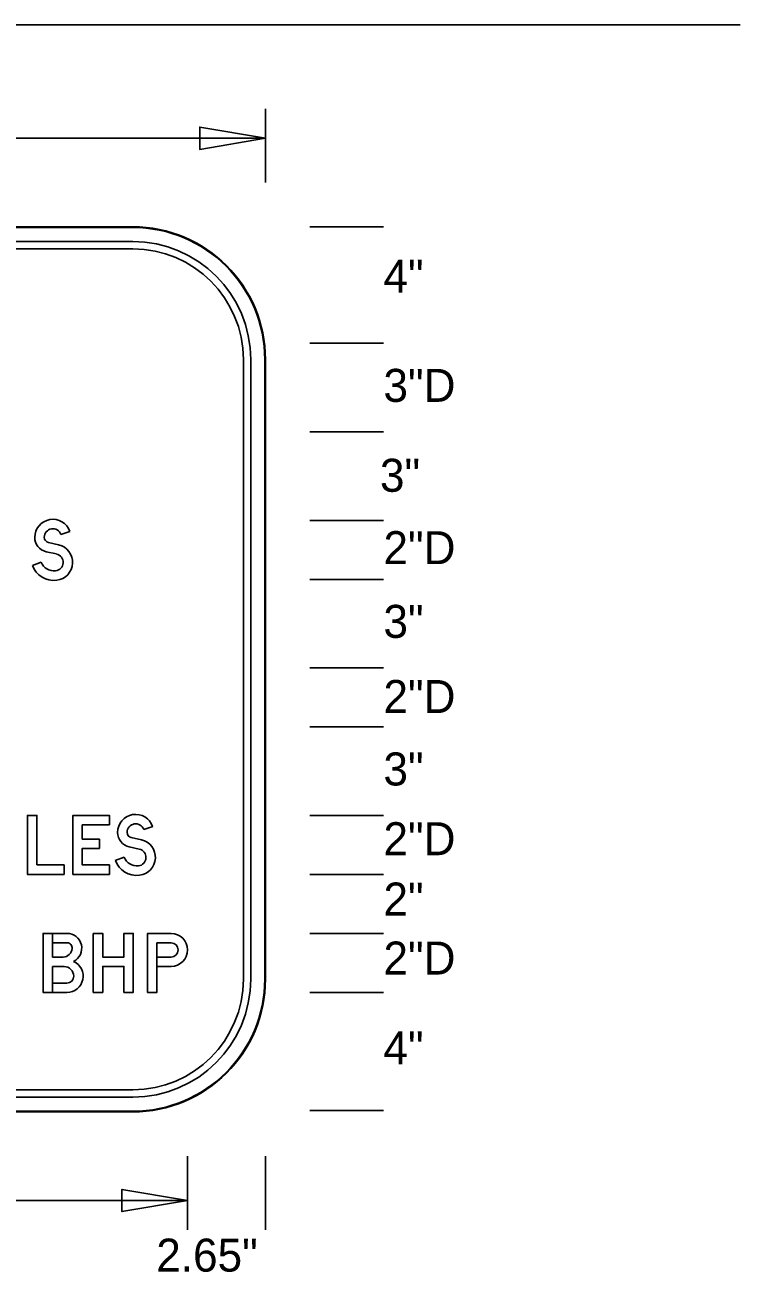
# Model space of a CAD drawing. Extents: x 0 to 770, y 0 to 495.
# Drawn here: x 694.1 to 770, y 197.7 to 330 of the extents above; entities that cross this region are included whole.
import ezdxf

# ---------------------------------------------------------------- set-up
doc = ezdxf.new("R2010")
doc.units = 0
for name, color, linetype in [('Default', 7, 'Continuous'), ('Dimension', 7, 'Continuous'), ('GSBWFill', 7, 'Continuous'), ('GSColorFill', 7, 'Continuous'), ('GSDims', 7, 'Continuous'), ('GSOutline', 7, 'Continuous'), ('SheetLines_dp', 7, 'Continuous')]:
    doc.layers.add(name, color=color, linetype=linetype)

msp = doc.modelspace()

# ---------------------------------------------------------------- linework, layer by layer
at = {"layer": 'Default'}
for p, q in [((697.92, 275.94), (698.86, 276.27)), ((697.92, 275.94), (698.86, 276.27)), ((697.92, 275.94), (698.86, 276.27)), ((696.37, 274.11), (697.45, 273.87)), ((696.37, 274.11), (697.45, 273.87)), ((696.37, 274.11), (697.45, 273.87)), ((697.67, 274.84), (696.59, 275.09)), ((697.67, 274.84), (696.59, 275.09)), ((697.67, 274.84), (696.59, 275.09)), ((695.84, 273), (694.9, 272.65)), ((695.84, 273), (694.9, 272.65)), ((695.84, 273), (694.9, 272.65)), ((706.71, 244.63), (707.66, 244.96)), ((706.71, 244.63), (707.66, 244.96)), ((706.71, 244.63), (707.66, 244.96)), ((706.47, 243.54), (705.39, 243.79)), ((706.47, 243.54), (705.39, 243.79)), ((706.47, 243.54), (705.39, 243.79)), ((705.16, 242.81), (706.24, 242.56)), ((705.16, 242.81), (706.24, 242.56)), ((705.16, 242.81), (706.24, 242.56)), ((704.63, 241.7), (703.69, 241.35)), ((704.63, 241.7), (703.69, 241.35)), ((704.63, 241.7), (703.69, 241.35)), ((698.56, 232.61), (697.03, 232.61)), ((708.11, 232.61), (709.61, 232.61)), ((708.11, 232.61), (709.61, 232.61)), ((697.03, 230.11), (698.25, 230.11)), ((697.03, 230.11), (698.25, 230.11)), ((697.03, 230.11), (698.25, 230.11)), ((708.11, 230.11), (709.61, 230.11)), ((696.02, 227.35), (698.56, 227.35))]:
    msp.add_line(p, q, dxfattribs=at)
for points in [[(695.37, 240.88), (698.25, 240.88), (698.25, 239.87), (694.37, 239.87), (694.37, 246.13), (695.37, 246.13)], [(695.37, 240.88), (698.25, 240.88), (698.25, 239.87), (694.37, 239.87), (694.37, 246.13), (695.37, 246.13)], [(695.37, 240.88), (698.25, 240.88), (698.25, 239.87), (694.37, 239.87), (694.37, 246.13), (695.37, 246.13)], [(703.07, 245.13), (700.19, 245.13), (700.19, 243.63), (702.01, 243.63), (702.01, 242.63), (700.19, 242.63), (700.19, 240.88), (703.07, 240.88), (703.07, 239.87), (699.19, 239.87), (699.19, 246.13), (703.07, 246.13)], [(703.07, 245.13), (700.19, 245.13), (700.19, 243.63), (702.01, 243.63), (702.01, 242.63), (700.19, 242.63), (700.19, 240.88), (703.07, 240.88), (703.07, 239.87), (699.19, 239.87), (699.19, 246.13), (703.07, 246.13)], [(703.07, 245.13), (700.19, 245.13), (700.19, 243.63), (702.01, 243.63), (702.01, 242.63), (700.19, 242.63), (700.19, 240.88), (703.07, 240.88), (703.07, 239.87), (699.19, 239.87), (699.19, 246.13), (703.07, 246.13)], [(701.35, 233.61), (702.35, 233.61), (702.35, 231.11), (704.6, 231.11), (704.6, 233.61), (705.6, 233.61), (705.6, 227.35), (704.6, 227.35), (704.6, 230.11), (702.35, 230.11), (702.35, 227.35), (701.35, 227.35)], [(701.35, 233.61), (702.35, 233.61), (702.35, 231.11), (704.6, 231.11), (704.6, 233.61), (705.6, 233.61), (705.6, 227.35), (704.6, 227.35), (704.6, 230.11), (702.35, 230.11), (702.35, 227.35), (701.35, 227.35)], [(701.35, 233.61), (702.35, 233.61), (702.35, 231.11), (704.6, 231.11), (704.6, 233.61), (705.6, 233.61), (705.6, 227.35), (704.6, 227.35), (704.6, 230.11), (702.35, 230.11), (702.35, 227.35), (701.35, 227.35)]]:
    msp.add_lwpolyline(points, close=True, dxfattribs=at)
for points in [[(698.56, 233.61), (696.02, 233.61), (696.02, 227.35)], [(698.15, 231.11), (697.03, 231.11), (697.03, 233.61), (696.02, 233.61), (696.02, 227.35), (697.03, 227.35), (697.03, 230.11)], [(698.15, 231.11), (697.03, 231.11), (697.03, 233.61), (696.02, 233.61), (696.02, 227.35), (697.03, 227.35), (697.03, 230.11)], [(698.56, 233.61), (697.03, 233.61), (697.03, 232.61), (698.56, 232.61)], [(698.56, 233.61), (697.03, 233.61), (697.03, 232.61), (698.56, 232.61)], [(709.61, 233.61), (707.11, 233.61), (707.11, 227.35), (708.11, 227.35), (708.11, 230.11)], [(709.61, 233.61), (707.11, 233.61), (707.11, 227.35), (708.11, 227.35), (708.11, 232.61)], [(709.61, 233.61), (707.11, 233.61), (707.11, 227.35), (708.11, 227.35), (708.11, 232.61)], [(697.03, 232.61), (697.03, 231.11), (698.15, 231.11)], [(709.61, 231.11), (708.11, 231.11), (708.11, 232.61), (709.61, 232.61)], [(709.61, 231.11), (708.11, 231.11), (708.11, 230.11), (709.61, 230.11)], [(709.61, 231.11), (708.11, 231.11), (708.11, 230.11), (709.61, 230.11)], [(698.56, 228.35), (697.03, 228.35), (697.03, 230.11)], [(698.56, 228.35), (697.03, 228.35), (697.03, 227.35), (698.56, 227.35)], [(698.56, 228.35), (697.03, 228.35), (697.03, 227.35), (698.56, 227.35)]]:
    msp.add_lwpolyline(points, dxfattribs=at)
for centre, radius, start, end in [((697.06, 275.64), 1.91, 19.1395, 180), ((697.06, 275.64), 1.91, 19.1395, 180), ((697.06, 275.64), 1.91, 19.1395, 180), ((697.06, 275.64), 0.908, 19.1395, 180), ((697.06, 275.64), 0.908, 19.1395, 180), ((697.06, 275.64), 0.908, 19.1395, 180), ((696.71, 275.64), 1.57, 180, 257.1915), ((696.71, 275.64), 1.57, 180, 257.1915), ((696.71, 275.64), 1.57, 180, 257.1915), ((696.71, 275.64), 0.563, 180, 257.1915), ((696.71, 275.64), 0.563, 180, 257.1915), ((696.71, 275.64), 0.563, 180, 257.1915), ((697.25, 272.98), 1.91, 276.7854, 77.1915), ((697.25, 272.98), 1.91, 276.7854, 77.1915), ((697.25, 272.98), 1.91, 276.7854, 77.1915), ((697.18, 273.51), 2.44, 200.6442, 276.7854), ((697.18, 273.51), 2.44, 200.6442, 276.7854), ((697.18, 273.51), 2.44, 200.6442, 276.7854), ((697.18, 273.51), 1.44, 200.6442, 276.7854), ((697.18, 273.51), 1.44, 200.6442, 276.7854), ((697.18, 273.51), 1.44, 200.6442, 276.7854), ((697.25, 272.98), 0.908, 276.7854, 77.1915), ((697.25, 272.98), 0.908, 276.7854, 77.1915), ((697.25, 272.98), 0.908, 276.7854, 77.1915), ((705.85, 244.33), 1.91, 19.1395, 180), ((705.85, 244.33), 1.91, 19.1395, 180), ((705.85, 244.33), 1.91, 19.1395, 180), ((705.85, 244.33), 0.908, 19.1395, 180), ((705.85, 244.33), 0.908, 19.1395, 180), ((705.85, 244.33), 0.908, 19.1395, 180), ((705.51, 244.33), 1.57, 180, 257.1915), ((705.51, 244.33), 1.57, 180, 257.1915), ((705.51, 244.33), 1.57, 180, 257.1915), ((705.51, 244.33), 0.563, 180, 257.1915), ((705.51, 244.33), 0.563, 180, 257.1915), ((705.51, 244.33), 0.563, 180, 257.1915), ((706.04, 241.68), 1.91, 276.7854, 77.1915), ((706.04, 241.68), 1.91, 276.7854, 77.1915), ((706.04, 241.68), 1.91, 276.7854, 77.1915), ((706.04, 241.68), 0.908, 276.7854, 77.1915), ((706.04, 241.68), 0.908, 276.7854, 77.1915), ((706.04, 241.68), 0.908, 276.7854, 77.1915), ((705.98, 242.21), 2.44, 200.6442, 276.7854), ((705.98, 242.21), 2.44, 200.6442, 276.7854), ((705.98, 242.21), 2.44, 200.6442, 276.7854), ((705.98, 242.21), 1.44, 200.6442, 276.7854), ((705.98, 242.21), 1.44, 200.6442, 276.7854), ((705.98, 242.21), 1.44, 200.6442, 276.7854), ((709.61, 231.86), 1.75, 270, 90), ((709.61, 231.86), 1.75, 270, 90), ((709.61, 231.86), 1.75, 270, 90), ((709.61, 231.86), 0.751, 270, 90), ((709.61, 231.86), 0.751, 270, 90), ((709.61, 231.86), 0.751, 270, 90)]:
    msp.add_arc(centre, radius, start, end, dxfattribs=at)
for centre, major_axis, start_param, end_param in [((698.56, 232.05), (0, 1.57), 3.604547, 6.283185), ((698.56, 232.05), (0, 1.57), 3.604547, 6.283185), ((698.56, 232.05), (0, 1.57), 3.604547, 6.283185), ((698.15, 232.08), (0, 0.97), 3.141593, 4.63539), ((698.15, 232.08), (0, 0.97), 3.141593, 4.63539), ((698.15, 232.08), (0, 0.97), 3.141593, 4.63539), ((698.56, 232.05), (0, 0.563), 4.63539, 6.283185), ((698.56, 232.05), (0, 0.563), 4.63539, 6.283185), ((698.56, 232.05), (0, 0.563), 4.63539, 6.283185), ((698.56, 229.07), (0, 1.72), 3.141593, 5.865119), ((698.56, 229.07), (0, 1.72), 3.141593, 5.865119), ((698.56, 229.07), (0, 1.72), 3.141593, 5.865119), ((698.25, 229.07), (0, 1.03), 4.712389, 6.283185), ((698.25, 229.07), (0, 1.03), 4.712389, 6.283185), ((698.25, 229.07), (0, 1.03), 4.712389, 6.283185), ((698.56, 229.07), (0, 0.72), 3.141593, 4.712389), ((698.56, 229.07), (0, 0.72), 3.141593, 4.712389), ((698.56, 229.07), (0, 0.72), 3.141593, 4.712389)]:
    msp.add_ellipse(centre, major_axis=major_axis, ratio=0.999993, start_param=start_param, end_param=end_param, dxfattribs=at)
at = {"layer": 'Dimension'}
for points in [[(719.63, 317.98), (712.65, 319.16), (712.65, 316.8)], [(711.36, 205.28), (704.39, 206.46), (704.39, 204.1)]]:
    msp.add_lwpolyline(points, close=True, dxfattribs=at)
at = {"layer": 'GSBWFill'}
for p, q in [((705.54, 308.59), (639.8, 308.59)), ((705.54, 307.02), (639.8, 307.02)), ((639.8, 306.24), (705.54, 306.24)), ((717.28, 294.5), (717.28, 228.76)), ((718.06, 228.76), (718.06, 294.5)), ((719.63, 228.76), (719.63, 294.5)), ((705.54, 217.02), (639.81, 217.02)), ((639.81, 216.24), (705.54, 216.24)), ((639.8, 214.67), (705.54, 214.67))]:
    msp.add_line(p, q, dxfattribs=at)
for centre, radius, start, end in [((705.54, 294.5), 14.09, 0, 90), ((705.54, 294.5), 12.52, 0, 90), ((705.54, 294.5), 11.74, 0, 90), ((705.54, 228.76), 12.52, 270, 0), ((705.54, 228.76), 11.74, 270, 0), ((705.54, 228.76), 14.09, 270, 0)]:
    msp.add_arc(centre, radius, start, end, dxfattribs=at)
at = {"layer": 'GSColorFill'}
for p, q in [((705.54, 308.59), (639.8, 308.59)), ((705.54, 308.59), (639.8, 308.59)), ((639.8, 308.51), (705.54, 308.51)), ((705.54, 307.02), (639.8, 307.02)), ((639.8, 306.24), (705.54, 306.24)), ((717.28, 294.5), (717.28, 228.76)), ((718.06, 228.76), (718.06, 294.5)), ((719.55, 294.5), (719.55, 228.76)), ((719.63, 228.76), (719.63, 294.5)), ((719.63, 228.76), (719.63, 294.5)), ((705.54, 217.02), (639.81, 217.02)), ((639.81, 216.24), (705.54, 216.24)), ((705.54, 214.75), (639.8, 214.75)), ((639.8, 214.67), (705.54, 214.67)), ((639.8, 214.67), (705.54, 214.67))]:
    msp.add_line(p, q, dxfattribs=at)
for centre, radius, start, end in [((705.54, 294.5), 14.09, 0, 90), ((705.54, 294.5), 14.09, 0, 90), ((705.54, 294.5), 14.01, 0, 90), ((705.54, 294.5), 12.52, 0, 90), ((705.54, 294.5), 11.74, 0, 90), ((705.54, 228.76), 14.09, 270, 0), ((705.54, 228.76), 12.52, 270, 0), ((705.54, 228.76), 11.74, 270, 0), ((705.54, 228.76), 14.09, 270, 0), ((705.54, 228.76), 14.01, 270, 0)]:
    msp.add_arc(centre, radius, start, end, dxfattribs=at)
at = {"layer": 'GSDims'}
for p, q in [((719.63, 313.28), (719.63, 321.11)), ((625.72, 317.98), (719.63, 317.98)), ((724.32, 308.59), (732.15, 308.59)), ((724.32, 296.22), (732.15, 296.22)), ((724.32, 296.22), (732.15, 296.22)), ((724.32, 286.83), (732.15, 286.83)), ((724.32, 286.83), (732.15, 286.83)), ((724.32, 277.44), (732.15, 277.44)), ((724.32, 277.44), (732.15, 277.44)), ((724.32, 271.18), (732.15, 271.18)), ((724.32, 271.18), (732.15, 271.18)), ((724.32, 261.79), (732.15, 261.79)), ((724.32, 261.79), (732.15, 261.79)), ((724.32, 255.53), (732.15, 255.53)), ((724.32, 255.53), (732.15, 255.53)), ((724.32, 246.13), (732.15, 246.13)), ((724.32, 246.13), (732.15, 246.13)), ((724.32, 239.87), (732.15, 239.87)), ((724.32, 239.87), (732.15, 239.87)), ((724.32, 233.61), (732.15, 233.61)), ((724.32, 233.61), (732.15, 233.61)), ((724.32, 227.35), (732.15, 227.35)), ((724.32, 227.35), (732.15, 227.35)), ((724.32, 214.83), (732.15, 214.83)), ((711.36, 209.98), (711.36, 202.15)), ((711.36, 209.98), (711.36, 202.15)), ((719.63, 209.98), (719.63, 202.15)), ((633.98, 205.28), (711.36, 205.28))]:
    msp.add_line(p, q, dxfattribs=at)
at = {"layer": 'GSOutline'}
for p, q in [((705.54, 308.59), (639.8, 308.59)), ((705.54, 307.02), (639.8, 307.02)), ((705.54, 306.24), (639.8, 306.24)), ((717.28, 228.76), (717.28, 294.5)), ((718.06, 228.76), (718.06, 294.5)), ((719.63, 228.76), (719.63, 294.5)), ((639.8, 217.02), (705.54, 217.02)), ((639.8, 216.24), (705.54, 216.24)), ((639.8, 214.67), (705.54, 214.67))]:
    msp.add_line(p, q, dxfattribs=at)
for centre, radius, start, end in [((705.54, 294.5), 14.09, 0, 90), ((705.54, 294.5), 12.52, 0, 90), ((705.54, 294.5), 11.74, 0, 90), ((705.54, 228.76), 12.52, 270, 0), ((705.54, 228.76), 11.74, 270, 0), ((705.54, 228.76), 14.09, 270, 0)]:
    msp.add_arc(centre, radius, start, end, dxfattribs=at)
at = {"layer": 'SheetLines_dp'}
msp.add_line((0, 330), (770, 330), dxfattribs=at)

# ---------------------------------------------------------------- texts
at = {"layer": 'Default'}
for s, p in [('4"', (732.15, 301.6)), ('3"D', (732.15, 290.01)), ('3"', (731.78, 280.47)), ('2"D', (732.15, 272.79)), ('3"', (732.15, 264.97)), ('2"D', (732.15, 257)), ('3"', (732.15, 249.31)), ('2"D', (732.15, 241.91)), ('2"', (732.15, 235.51)), ('2"D', (732.15, 229.25)), ('4"', (732.15, 219.72)), ('2.65"', (708.04, 197.73))]:
    msp.add_text(s, height=3.5, dxfattribs=at).set_placement(p)

doc.saveas('drawing.dxf')
